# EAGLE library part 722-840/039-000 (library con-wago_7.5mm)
Serie 722, Federleiste mit Verriegelungsklinken / Series 722, Female connector with locking levers Polzahl / Pole No.: 10 Farbe / Color: lichtgrau / light gray Stand: 01.01.2012. Die jeweils aktuellen Daten zu diesem Artikel finden Sie in unserem Produktkatalog, den Sie unter www.wago.com einsehen können. As of: 01/01/2012. Please find the newest data for this article in our product catalogue, which can be viewed under www.wago.com.
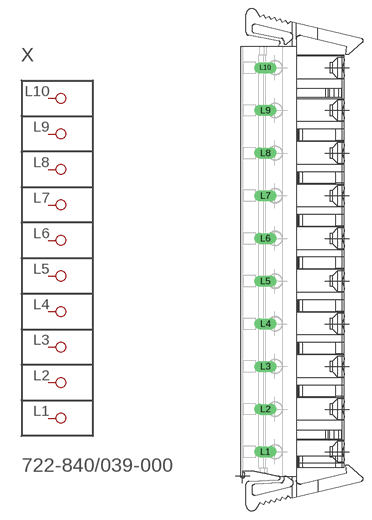
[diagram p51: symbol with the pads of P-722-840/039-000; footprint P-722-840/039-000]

Designator prefix X

## 722-840/039-000  [P-722-840/039-000]
L1  P1
L2  P2
L3  P3
L4  P4
L5  P5
L6  P6
L7  P7
L8  P8
L9  P9
L10  P10

## Footprint P-722-840/039-000 (pad centres in mm)
drill 1.3 long: L1 -5.946,-33.75; L2 -5.946,-26.25; L3 -5.946,-18.75; L4 -5.946,-11.25; L5 -5.946,-3.75; L6 -5.946,3.75; L7 -5.946,11.25; L8 -5.946,18.75; L9 -5.946,26.25; L10 -5.946,33.75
